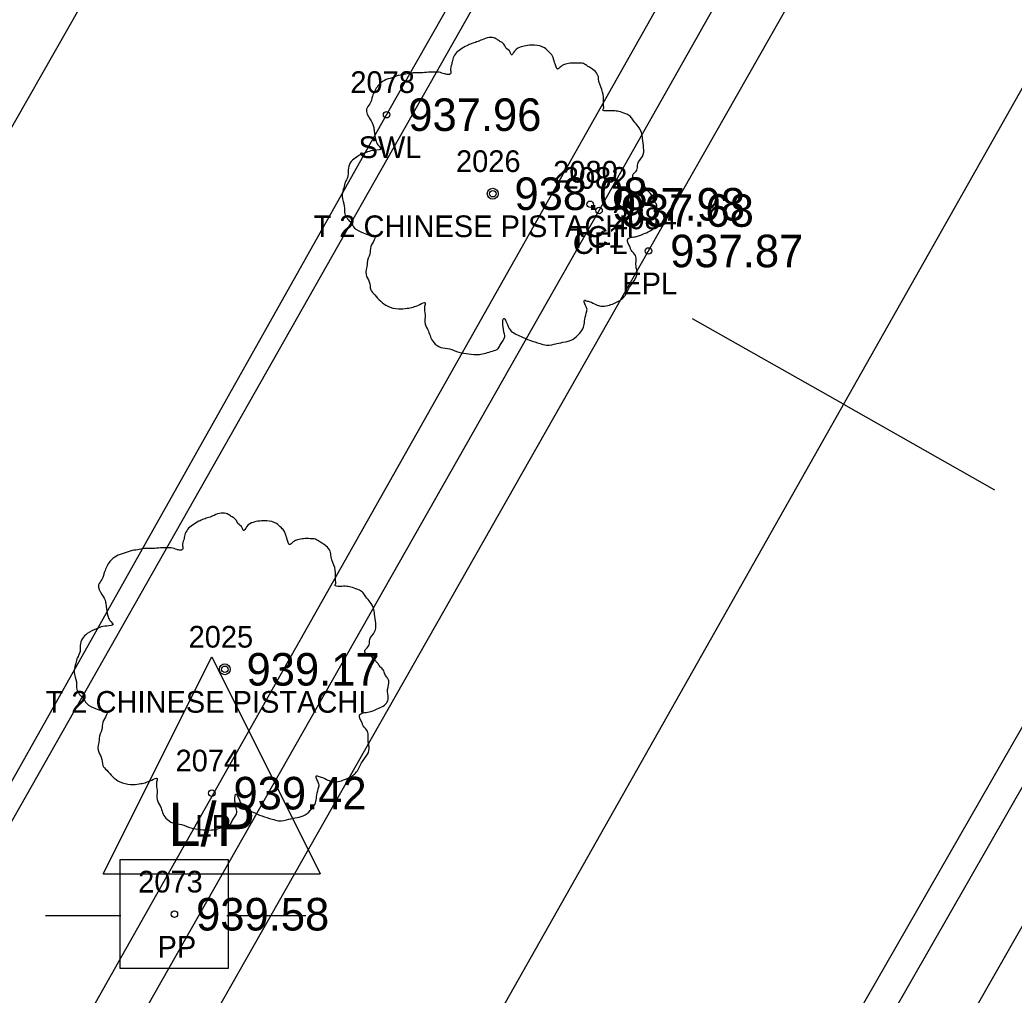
# Model space of a CAD drawing. Extents: x 1575382 to 1578175, y 1099175 to 1101955.
# Drawn here: x 1576635.91 to 1576681.73, y 1099999.91 to 1100044.83 of the extents above; entities that cross this region are included whole.
import ezdxf

# ---------------------------------------------------------------- set-up
doc = ezdxf.new("R2010")
doc.units = 0
for name, color, linetype in [('RD_EX_Conc', 7, 'Continuous'), ('RD_EX_Conc_txCode', 7, 'Continuous'), ('RD_EX_Road', 7, 'Continuous'), ('RD_EX_Road_txCode', 7, 'Continuous'), ('RD_EX_TX_Conc_ELEV', 7, 'Continuous'), ('RD_EX_TX_Road_ELEV', 7, 'Continuous'), ('RD_EX_TX_UT_ELEV', 7, 'Continuous'), ('RD_EX_TX_VEG_ELEV', 7, 'Continuous'), ('RD_EX_UT', 7, 'Continuous'), ('RD_EX_UT_txCode', 7, 'Continuous'), ('RD_EX_VEG', 7, 'Continuous'), ('RD_EX_VEG_txCode', 7, 'Continuous'), ('RD_HC_Cl', 7, 'Continuous'), ('RD_HC_Data_Tic', 7, 'Continuous'), ('RD_HC_Survey_ELEV', 7, 'Continuous'), ('RD_SMD_Locator', 7, 'Continuous')]:
    doc.layers.add(name, color=color, linetype=linetype)

msp = doc.modelspace()

# ---------------------------------------------------------------- linework, layer by layer
at = {"layer": 'RD_EX_Conc'}
for points in [[(1576537.526, 1099904.469), (1576543.864, 1099909.524), (1576562.156, 1099910.987), (1576591.509, 1099962.437), (1576615.66, 1100005.023), (1576615.66, 1100005.023), (1576639.955, 1100047.654), (1576665.605, 1100092.866), (1576689.568, 1100135.166), (1576714.68, 1100179.661), (1576738.987, 1100222.526), (1576763.599, 1100265.874), (1576774.843, 1100284.485), (1576788.688, 1100308.171), (1576806.144, 1100353.343), (1576815.02, 1100384.279), (1576820.349, 1100399.915), (1576825.225, 1100406.934), (1576832.152, 1100418.175), (1576835.036, 1100423.107), (1576847.134, 1100416.346), (1576868.436, 1100408.229), (1576872.091, 1100412.695)], [(1576592.247, 1099913.589), (1576580.198, 1099912.487), (1576604.174, 1099954.859), (1576628.847, 1099997.887), (1576628.847, 1099997.887), (1576652.81, 1100040.468), (1576678.277, 1100085.173), (1576702.194, 1100127.32), (1576727.433, 1100172.039), (1576752.103, 1100215.386), (1576776.492, 1100258.763), (1576787.999, 1100277.344), (1576801.961, 1100301.42), (1576820.181, 1100348.297), (1576829.188, 1100379.588), (1576833.875, 1100393.406), (1576838.317, 1100402.428), (1576861.822, 1100391.113)], [(1576569.868, 1099888.686), (1576574.844, 1099890.862), (1576574.844, 1099890.862), (1576579.65, 1099894.152), (1576584.72, 1099899.292), (1576592.679, 1099913.301), (1576613.452, 1099949.723), (1576638.024, 1099992.781), (1576638.024, 1099992.781), (1576662.599, 1100036.053), (1576687.141, 1100079.444), (1576711.907, 1100122.93), (1576736.416, 1100166.347), (1576761.24, 1100209.96), (1576785.667, 1100253.173), (1576809.571, 1100296.248), (1576834.314, 1100340.558), (1576852.459, 1100373.219), (1576852.459, 1100373.219), (1576859.244, 1100385.101)], [(1576664.483, 1099978.734), (1576688.587, 1100020.786), (1576713.4, 1100064.494), (1576739.812, 1100111.259), (1576742.954, 1100115.664), (1576746.942, 1100119.009)], [(1576604.877, 1099870.264), (1576606.176, 1099869.972), (1576617.178, 1099889.586), (1576642.123, 1099933.618), (1576667.46, 1099977.419), (1576667.46, 1099977.419), (1576691.066, 1100018.787), (1576716.011, 1100062.956), (1576735.124, 1100096.928), (1576741.874, 1100105.044), (1576743.621, 1100107.754)]]:
    msp.add_lwpolyline(points, dxfattribs=at)
at = {"layer": 'RD_EX_Road'}
for points in [[(1576574.844, 1099890.862), (1576581.171, 1099887.16), (1576595.394, 1099911.974), (1576615.874, 1099948.174), (1576640.557, 1099991.404), (1576640.557, 1099991.404), (1576664.878, 1100034.189), (1576689.843, 1100078.058), (1576714.218, 1100121.186), (1576739.079, 1100164.658), (1576764.147, 1100209.109), (1576788.309, 1100251.8), (1576812.145, 1100294.456), (1576837.057, 1100339.374), (1576855.378, 1100371.527), (1576853.98, 1100372.475), (1576862.984, 1100388.862), (1576865.16, 1100391.948), (1576873.145, 1100402.798), (1576877.449, 1100410.316)], [(1576663.307, 1099979.534), (1576687.432, 1100021.526), (1576712.032, 1100065.104), (1576738.416, 1100112.144), (1576760.611, 1100151.412), (1576785.777, 1100195.961), (1576800.589, 1100221.872), (1576817.543, 1100252.084), (1576858.248, 1100324.631), (1576880.454, 1100364.005), (1576883.5, 1100369.448), (1576896.98, 1100397.709)]]:
    msp.add_lwpolyline(points, dxfattribs=at)
at = {"layer": 'RD_EX_UT'}
for p, q in [((1576639.753, 1100005.489), (1576644.753, 1100015.489)), ((1576644.753, 1100015.489), (1576649.753, 1100005.489)), ((1576645.522, 1100006.145), (1576640.522, 1100006.145)), ((1576640.522, 1100006.145), (1576640.522, 1100001.145)), ((1576645.522, 1100001.145), (1576645.522, 1100006.145)), ((1576639.753, 1100005.489), (1576649.753, 1100005.489)), ((1576637.091, 1100003.583), (1576640.56, 1100003.583)), ((1576645.451, 1100003.583), (1576649.091, 1100003.583)), ((1576640.522, 1100001.145), (1576645.522, 1100001.145))]:
    msp.add_line(p, q, dxfattribs=at)
at = {"layer": 'RD_EX_VEG'}
msp.add_lwpolyline([(1576857.287, 1100385.555), (1576853.725, 1100387.584), (1576857.137, 1100393.159), (1576838.521, 1100401.595), (1576823.142, 1100348.953), (1576803.691, 1100301.627), (1576767.36, 1100240.355), (1576582.077, 1099913.71), (1576591.587, 1099914.9), (1576857.287, 1100385.555)], dxfattribs=at)
for centre, radius in [((1576657.702, 1100036.826), 0.25), ((1576657.69, 1100036.808), 0.0001), ((1576645.354, 1100014.918), 0.25), ((1576645.341, 1100014.899), 0.0001)]:
    msp.add_circle(centre, radius, dxfattribs=at)
for points in [[(1576657.834, 1100043.994), (1576657.534, 1100044.019), (1576657.21, 1100043.919), (1576656.96, 1100043.819), (1576656.735, 1100043.744), (1576656.51, 1100043.644), (1576656.21, 1100043.469), (1576655.985, 1100043.269), (1576655.86, 1100043.019), (1576655.81, 1100042.794), (1576655.76, 1100042.519), (1576655.76, 1100042.344), (1576655.635, 1100042.319), (1576655.485, 1100042.344), (1576655.235, 1100042.419), (1576654.986, 1100042.419), (1576654.736, 1100042.419), (1576654.386, 1100042.394), (1576654.036, 1100042.394), (1576653.761, 1100042.344), (1576653.436, 1100042.294), (1576653.061, 1100042.169), (1576652.712, 1100042.044), (1576652.412, 1100041.795), (1576652.162, 1100041.32), (1576652.037, 1100040.97), (1576651.887, 1100040.72), (1576652.037, 1100040.27), (1576652.212, 1100039.92), (1576652.237, 1100039.72), (1576652.312, 1100039.296), (1576652.412, 1100039.071), (1576652.537, 1100038.871), (1576652.462, 1100038.846), (1576652.087, 1100038.796), (1576651.787, 1100038.696), (1576651.362, 1100038.471), (1576651.137, 1100038.246), (1576651.037, 1100037.921), (1576651.012, 1100037.571), (1576650.912, 1100037.372), (1576650.837, 1100037.097), (1576650.812, 1100037.022), (1576650.762, 1100036.697), (1576650.862, 1100036.247), (1576650.887, 1100035.897), (1576651.012, 1100035.672), (1576651.162, 1100035.497), (1576651.337, 1100035.247), (1576651.737, 1100035.023), (1576652.062, 1100034.923), (1576652.262, 1100034.898), (1576652.087, 1100034.398), (1576652.037, 1100034.048), (1576651.912, 1100033.648), (1576651.912, 1100033.573), (1576651.862, 1100033.098), (1576652.012, 1100032.773), (1576652.087, 1100032.399), (1576652.262, 1100032.174), (1576652.537, 1100031.874), (1576652.861, 1100031.649), (1576653.361, 1100031.524), (1576653.761, 1100031.549), (1576654.336, 1100031.724), (1576654.586, 1100031.799), (1576654.561, 1100031.624), (1576654.586, 1100031.249), (1576654.586, 1100030.824), (1576654.736, 1100030.5), (1576654.836, 1100030.225), (1576654.986, 1100029.975), (1576655.31, 1100029.75), (1576655.71, 1100029.675), (1576656.135, 1100029.525), (1576656.585, 1100029.45), (1576657.085, 1100029.425), (1576657.684, 1100029.575), (1576657.959, 1100029.7), (1576658.059, 1100029.875), (1576658.259, 1100030.25), (1576658.209, 1100030.475), (1576658.234, 1100031.074), (1576658.334, 1100030.899), (1576658.509, 1100030.549), (1576659.009, 1100030.25), (1576659.409, 1100030.075), (1576659.883, 1100029.925), (1576660.183, 1100029.85), (1576660.658, 1100029.925), (1576661.033, 1100030), (1576661.408, 1100030.125), (1576661.708, 1100030.4), (1576661.883, 1100030.674), (1576661.933, 1100030.949), (1576662.007, 1100031.324), (1576662.057, 1100031.499)], [(1576662.057, 1100031.499), (1576661.983, 1100031.674), (1576661.933, 1100031.924), (1576662.007, 1100031.899), (1576662.182, 1100031.849), (1576662.457, 1100031.724), (1576662.682, 1100031.649), (1576663.007, 1100031.674), (1576663.282, 1100031.774), (1576663.732, 1100032.049), (1576664.007, 1100032.524), (1576664.281, 1100032.923), (1576664.356, 1100033.248), (1576664.306, 1100033.473), (1576664.281, 1100033.973), (1576664.082, 1100034.223), (1576664.032, 1100034.348), (1576663.932, 1100034.748), (1576664.007, 1100034.798), (1576664.281, 1100034.848), (1576664.656, 1100034.973), (1576664.931, 1100035.097), (1576665.156, 1100035.272), (1576665.231, 1100035.497), (1576665.206, 1100035.897), (1576665.256, 1100036.297), (1576665.181, 1100036.447), (1576665.081, 1100036.597), (1576665.006, 1100036.797), (1576664.856, 1100036.947), (1576664.756, 1100037.097), (1576664.656, 1100037.197), (1576664.531, 1100037.347), (1576664.356, 1100037.471), (1576664.207, 1100037.521), (1576664.157, 1100037.671), (1576664.306, 1100037.871), (1576664.356, 1100037.971), (1576664.381, 1100038.196), (1576664.606, 1100038.546), (1576664.656, 1100038.946), (1576664.606, 1100039.371), (1576664.556, 1100039.646), (1576664.406, 1100039.92), (1576664.207, 1100040.17), (1576664.082, 1100040.345), (1576663.907, 1100040.47), (1576663.582, 1100040.595), (1576663.332, 1100040.645), (1576662.982, 1100040.645), (1576662.782, 1100040.695), (1576662.807, 1100040.745), (1576662.807, 1100040.895), (1576662.807, 1100041.17), (1576662.732, 1100041.62), (1576662.582, 1100042.119), (1576662.582, 1100042.144), (1576662.482, 1100042.394), (1576662.257, 1100042.594), (1576662.082, 1100042.694), (1576661.883, 1100042.819), (1576661.633, 1100042.844), (1576661.333, 1100042.844), (1576661.058, 1100042.794), (1576660.858, 1100042.694), (1576660.683, 1100042.569), (1576660.608, 1100042.719), (1576660.508, 1100043.019), (1576660.458, 1100043.169), (1576660.308, 1100043.344), (1576660.083, 1100043.544), (1576659.633, 1100043.669), (1576659.009, 1100043.594), (1576658.709, 1100043.394), (1576658.559, 1100043.219), (1576658.509, 1100043.344), (1576658.309, 1100043.544), (1576658.209, 1100043.719), (1576658.034, 1100043.844), (1576657.884, 1100043.944), (1576657.784, 1100043.994)], [(1576645.486, 1100022.085), (1576645.186, 1100022.11), (1576644.861, 1100022.01), (1576644.611, 1100021.91), (1576644.386, 1100021.835), (1576644.161, 1100021.735), (1576643.862, 1100021.56), (1576643.637, 1100021.36), (1576643.512, 1100021.11), (1576643.462, 1100020.885), (1576643.412, 1100020.611), (1576643.412, 1100020.436), (1576643.287, 1100020.411), (1576643.137, 1100020.436), (1576642.887, 1100020.511), (1576642.637, 1100020.511), (1576642.387, 1100020.511), (1576642.037, 1100020.486), (1576641.687, 1100020.486), (1576641.413, 1100020.436), (1576641.088, 1100020.386), (1576640.713, 1100020.261), (1576640.363, 1100020.136), (1576640.063, 1100019.886), (1576639.813, 1100019.411), (1576639.688, 1100019.061), (1576639.538, 1100018.811), (1576639.688, 1100018.362), (1576639.863, 1100018.012), (1576639.888, 1100017.812), (1576639.963, 1100017.387), (1576640.063, 1100017.162), (1576640.188, 1100016.962), (1576640.113, 1100016.937), (1576639.738, 1100016.887), (1576639.438, 1100016.787), (1576639.014, 1100016.562), (1576638.789, 1100016.337), (1576638.689, 1100016.012), (1576638.664, 1100015.663), (1576638.564, 1100015.463), (1576638.489, 1100015.188), (1576638.464, 1100015.113), (1576638.414, 1100014.788), (1576638.514, 1100014.338), (1576638.539, 1100013.988), (1576638.664, 1100013.763), (1576638.814, 1100013.589), (1576638.989, 1100013.339), (1576639.388, 1100013.114), (1576639.713, 1100013.014), (1576639.913, 1100012.989), (1576639.738, 1100012.489), (1576639.688, 1100012.139), (1576639.563, 1100011.739), (1576639.563, 1100011.664), (1576639.513, 1100011.19), (1576639.663, 1100010.865), (1576639.738, 1100010.49), (1576639.913, 1100010.265), (1576640.188, 1100009.965), (1576640.513, 1100009.74), (1576641.013, 1100009.615), (1576641.413, 1100009.64), (1576641.987, 1100009.815), (1576642.237, 1100009.89), (1576642.212, 1100009.715), (1576642.237, 1100009.34), (1576642.237, 1100008.916), (1576642.387, 1100008.591), (1576642.487, 1100008.316), (1576642.637, 1100008.066), (1576642.962, 1100007.841), (1576643.362, 1100007.766), (1576643.787, 1100007.616), (1576644.236, 1100007.541), (1576644.736, 1100007.516), (1576645.336, 1100007.666), (1576645.611, 1100007.791), (1576645.711, 1100007.966), (1576645.911, 1100008.341), (1576645.861, 1100008.566), (1576645.886, 1100009.166), (1576645.986, 1100008.991), (1576646.161, 1100008.641), (1576646.66, 1100008.341), (1576647.06, 1100008.166), (1576647.535, 1100008.016), (1576647.835, 1100007.941), (1576648.31, 1100008.016), (1576648.684, 1100008.091), (1576649.059, 1100008.216), (1576649.359, 1100008.491), (1576649.534, 1100008.766), (1576649.584, 1100009.041), (1576649.659, 1100009.415), (1576649.709, 1100009.59)], [(1576649.709, 1100009.59), (1576649.634, 1100009.765), (1576649.584, 1100010.015), (1576649.659, 1100009.99), (1576649.834, 1100009.94), (1576650.109, 1100009.815), (1576650.334, 1100009.74), (1576650.659, 1100009.765), (1576650.933, 1100009.865), (1576651.383, 1100010.14), (1576651.658, 1100010.615), (1576651.933, 1100011.015), (1576652.008, 1100011.34), (1576651.958, 1100011.564), (1576651.933, 1100012.064), (1576651.733, 1100012.314), (1576651.683, 1100012.439), (1576651.583, 1100012.839), (1576651.658, 1100012.889), (1576651.933, 1100012.939), (1576652.308, 1100013.064), (1576652.583, 1100013.189), (1576652.808, 1100013.364), (1576652.883, 1100013.589), (1576652.858, 1100013.988), (1576652.908, 1100014.388), (1576652.833, 1100014.538), (1576652.733, 1100014.688), (1576652.658, 1100014.888), (1576652.508, 1100015.038), (1576652.408, 1100015.188), (1576652.308, 1100015.288), (1576652.183, 1100015.438), (1576652.008, 1100015.563), (1576651.858, 1100015.613), (1576651.808, 1100015.763), (1576651.958, 1100015.963), (1576652.008, 1100016.062), (1576652.033, 1100016.287), (1576652.258, 1100016.637), (1576652.308, 1100017.037), (1576652.258, 1100017.462), (1576652.208, 1100017.737), (1576652.058, 1100018.012), (1576651.858, 1100018.262), (1576651.733, 1100018.436), (1576651.558, 1100018.561), (1576651.233, 1100018.686), (1576650.983, 1100018.736), (1576650.634, 1100018.736), (1576650.434, 1100018.786), (1576650.459, 1100018.836), (1576650.459, 1100018.986), (1576650.459, 1100019.261), (1576650.384, 1100019.711), (1576650.234, 1100020.211), (1576650.234, 1100020.236), (1576650.134, 1100020.486), (1576649.909, 1100020.685), (1576649.734, 1100020.785), (1576649.534, 1100020.91), (1576649.284, 1100020.935), (1576648.984, 1100020.935), (1576648.709, 1100020.885), (1576648.509, 1100020.785), (1576648.335, 1100020.66), (1576648.26, 1100020.81), (1576648.16, 1100021.11), (1576648.11, 1100021.26), (1576647.96, 1100021.435), (1576647.735, 1100021.635), (1576647.285, 1100021.76), (1576646.66, 1100021.685), (1576646.36, 1100021.485), (1576646.21, 1100021.31), (1576646.161, 1100021.435), (1576645.961, 1100021.635), (1576645.861, 1100021.81), (1576645.686, 1100021.935), (1576645.536, 1100022.035), (1576645.436, 1100022.085)]]:
    msp.add_spline(points, degree=3, dxfattribs=at)
at = {"layer": 'RD_HC_Cl'}
msp.add_line((1576639.689, 1099966.694), (1576888.29, 1100406.318), dxfattribs=at)
at = {"layer": 'RD_HC_Data_Tic'}
for q in [(1576666.9, 1100031.067), (1576680.828, 1100023.191)]:
    msp.add_line((1576673.864, 1100027.129), q, dxfattribs=at)
at = {"layer": 'RD_SMD_Locator'}
for centre in [(1576652.81, 1100040.468), (1576657.702, 1100036.826), (1576662.194, 1100036.338), (1576662.599, 1100036.053), (1576664.878, 1100034.189), (1576645.354, 1100014.918), (1576644.753, 1100009.213), (1576643.031, 1100003.636)]:
    msp.add_circle(centre, 0.15, dxfattribs=at)

# ---------------------------------------------------------------- texts
at = {"layer": 'RD_EX_Conc_txCode'}
for s, p in [('2078', (1576651.14, 1100041.468)), ('SWL', (1576651.518, 1100038.468)), ('2080', (1576660.486, 1100037.338)), ('2082', (1576660.93, 1100037.053)), ('TC1', (1576661.234, 1100034.338)), ('CFL', (1576661.394, 1100034.053))]:
    msp.add_text(s, height=1, dxfattribs=at).set_placement(p)
at = {"layer": 'RD_EX_Road_txCode'}
for s, p in [('2084', (1576663.208, 1100035.189)), ('EPL', (1576663.673, 1100032.189))]:
    msp.add_text(s, height=1, dxfattribs=at).set_placement(p)
at = {"layer": 'RD_EX_TX_Conc_ELEV'}
for s, p in [('937.96', (1576653.81, 1100039.718)), ('937.98', (1576663.194, 1100035.588)), ('937.68', (1576663.599, 1100035.303))]:
    msp.add_text(s, height=1.5, dxfattribs=at).set_placement(p)
at = {"layer": 'RD_EX_TX_Road_ELEV'}
msp.add_text('937.87', height=1.5, dxfattribs=at).set_placement((1576665.878, 1100033.439))
at = {"layer": 'RD_EX_TX_UT_ELEV'}
msp.add_text('939.42', height=1.5, dxfattribs=at).set_placement((1576645.753, 1100008.463))
at = {"layer": 'RD_EX_TX_VEG_ELEV'}
for s, p in [('938.08', (1576658.702, 1100036.076)), ('939.17', (1576646.354, 1100014.168))]:
    msp.add_text(s, height=1.5, dxfattribs=at).set_placement(p)
at = {"layer": 'RD_EX_UT'}
msp.add_text('L/P', height=2, dxfattribs=at).set_placement((1576642.745, 1100006.771))
at = {"layer": 'RD_EX_UT_txCode'}
for s, p in [('2074', (1576643.084, 1100010.213)), ('LP', (1576643.997, 1100007.213)), ('2073', (1576641.362, 1100004.636)), ('PP', (1576642.252, 1100001.636))]:
    msp.add_text(s, height=1, dxfattribs=at).set_placement(p)
at = {"layer": 'RD_EX_VEG_txCode'}
for s, p in [('2026', (1576656.009, 1100037.826)), ('T 2 CHINESE PISTACHI', (1576649.443, 1100034.826)), ('2025', (1576643.685, 1100015.918)), ('T 2 CHINESE PISTACHI', (1576637.094, 1100012.918))]:
    msp.add_text(s, height=1, dxfattribs=at).set_placement(p)
at = {"layer": 'RD_HC_Survey_ELEV'}
msp.add_text('939.58', height=1.5, dxfattribs=at).set_placement((1576644.031, 1100002.886))

doc.saveas('drawing.dxf')
